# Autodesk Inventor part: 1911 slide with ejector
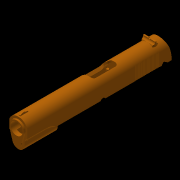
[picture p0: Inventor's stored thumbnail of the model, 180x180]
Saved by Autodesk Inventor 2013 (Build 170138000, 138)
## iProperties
Created: 2012-12
Part Number: 1911 slide with ejector
Material: Generic
Document SubType Name: Modeling
Designer: John
Density: 1 g/cm^3
Author: John
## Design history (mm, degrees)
sketch "Sketch1"
  geometry: L1 (-11.633, -12.598)-(-11.633, 4.424); L2 (11.633, -12.598)-(11.633, 4.424); L3 (-8.128, -16.129)-(-8.128, -12.598); L4 (8.128, -16.129)-(8.128, -12.598); L5 (-11.633, -12.598)-(-8.128, -12.598); L6 (8.128, -12.598)-(11.633, -12.598); C1 r 8.877 at (0, 0); C2 r 6.35 at (0, -16.129); A1 r 12.446 centre (0, 0) between (11.633, 4.424) and (-11.633, 4.424); A2 r 8.128 centre (0, -16.129) between (-8.128, -16.129) and (8.128, -16.129); 1 further point
  constraints: 12 end point, 4 centre point, 4 perpendicular, 4 point on circle, 3 coincident, 2 tangent
  dimensions: "d9" = 12.7 diameter of C2
extrude "Extrusion1" new body sketch "Sketch1" distance "d10" = 43.1292; taper "d11" = 0 deg
sketch "Sketch2"
  geometry: L1 (11.633, -12.598)-(11.633, 4.424) reference; L2 (-11.633, 4.424)-(-11.633, -12.598) reference; L3 (-8.877, 0)-(-8.877, -12.598); L4 (8.877, 0)-(8.877, -12.598); L5 (-11.633, -12.598)-(-8.877, -12.598); L6 (8.877, -12.598)-(11.633, -12.598); A1 r 8.877 centre (0, 0) between (-8.877, 0) and (8.877, 0) reference; A2 r 12.446 centre (0, 0) between (11.633, 4.424) and (-11.633, 4.424) reference
  constraints: 8 end point, 6 perpendicular, 2 point on circle, 2 tangent
extrude "Extrusion2" join sketch "Sketch2" distance "d12" = 138.6332; taper "d13" = 0 deg
sketch "Sketch3"
  geometry: L1 (181.762, 17.022)-(181.762, 0) reference; L2 (181.762, 17.022)-(181.762, 25.044) reference; L3 (181.762, 0)-(189.144, 0); A1 r 46.177 centre (142.967, 0) between (189.144, 0) and (181.762, 25.044); 1 further point
  constraints: 2 end point, 2 point on circle, 1 centre point, 1 perpendicular
extrude "Extrusion3" join sketch "Sketch3" stored distance "d15" = 24.892; taper "d16" = 0 deg
sketch "Sketch4"
  geometry: L1 (-11.633, -12.598)-(-11.633, 4.424) reference; L2 (11.633, 4.424)-(11.633, -12.598) reference; L3 (-11.633, 1.975)-(-14.32, 1.975); L4 (-14.32, 1.975)-(-14.32, 15.401); L5 (-14.32, 15.401)-(14.052, 15.401); L6 (14.052, 15.401)-(14.052, 2.651); L7 (14.052, 2.651)-(11.633, 2.651); A1 r 12.446 centre (0, 0) between (11.633, 4.424) and (-11.633, 4.424) reference
  constraints: 10 end point, 3 perpendicular, 2 parallel, 2 point on line
extrude "Extrusion4" cut sketch "Sketch4" stored distance "d17" = 24.892; taper "d18" = 0 deg
sketch "Sketch5"
  geometry: L1 (-19.761, 43.129)-(-19.761, -146.015) reference; L2 (3.505, -146.015)-(-19.761, -146.015) reference; L3 (3.505, 43.129)-(3.505, -146.015) reference; L4 (-16.256, 43.129)-(-16.256, 0) reference; L5 (3.505, -144.665)-(3.505, -148.55); L6 (3.505, -148.55)-(-19.761, -148.55); L7 (-19.761, -148.55)-(-19.761, -144.665); A1 r 50.8 centre (-8.128, -95.215) between (-19.761, -144.665) and (3.505, -144.665); A2 r 50.8 centre (-8.128, -95.215) between (3.505, -45.765) and (-19.761, -45.765); 1 further point
  constraints: 6 end point, 4 point on circle, 4 point on line, 2 centre point, 2 parallel, 1 perpendicular
sketch "Sketch6"
  geometry: A1 r 46.177 centre (-12.598, -142.967) between (-12.598, -189.144) and (12.446, -181.762); 1 further point
  constraints: 2 point on circle, 1 centre point
sketch "Sketch8"
  geometry: L1 (3.505, 43.129)-(0, 43.129) reference; L2 (5.944, 43.129)-(0, 43.129); L3 (5.944, 43.129)-(5.944, 1.079); L4 (5.944, 1.079)-(0, 1.079); L5 (0, 20.366)-(0, 43.129); A1 r 34.267 centre (34.267, 20.366) between (0, 20.366) and (5.944, 1.079); 1 further point
  constraints: 8 end point, 2 perpendicular, 2 point on circle, 1 centre point, 1 collinear, 1 tangent
revolve "Revolution1" sketch "Sketch8" stored, may be unused: angle "d23" = 90 deg
mirror "Mirror1"
sketch "Sketch9"
  geometry: L1 (-9.576, -9.601)-(9.576, -9.601); L2 (-11.633, 4.424)-(-11.633, -7.178) reference; L3 (-8.128, -12.598)-(-11.633, -12.598) reference; L4 (11.633, -7.178)-(11.633, 4.424) reference; L5 (11.633, -12.598)-(8.128, -12.598) reference; L6 (-11.633, -7.178)-(-11.633, -12.598); L7 (11.633, -12.598)-(11.633, -7.178); L8 (-9.576, -7.036)-(9.576, -7.036); L9 (-9.576, -9.601)-(-9.576, -7.036); L10 (9.576, -9.601)-(9.576, -7.036); A1 r 12.446 centre (0, 0) between (11.633, 4.424) and (-11.633, 4.424) reference; 1 further point
  constraints: 12 end point, 3 perpendicular, 1 parallel
extrude "Extrusion5" cut sketch "Sketch9" stored distance "d31" = 25.4; taper "d32" = 0 deg
sketch "Sketch10"
  geometry: L1 (12.446, 0)-(12.446, -181.762) reference; L2 (-12.598, -37.861)-(-12.598, -189.144) reference; L3 (12.446, -181.762)-(-12.598, -181.762); L4 (-12.598, -181.762)-(13.56, -181.762); L5 (13.56, -181.762)-(13.56, -201.516); L6 (13.56, -201.516)-(-12.598, -201.516); L7 (-12.598, -201.516)-(-12.598, -181.762); 2 further points
  constraints: 10 end point, 2 parallel, 2 perpendicular, 1 horizontal, 1 point on line
extrude "Extrusion6" cut sketch "Sketch10" stored distance "d33" = 8.001; taper "d34" = 0 deg
sketch "Sketch11"
  geometry: L1 (4.877, -2.565)-(4.877, -5.563) reference; L2 (-2.756, -5.563)-(4.877, -5.563) reference; L3 (-2.756, 11.46)-(-2.756, -5.563) reference; L4 (4.877, 18.821)-(4.877, 0) reference; L5 (4.877, 0)-(-0.698, 0) reference; L6 (-0.698, 0)-(-0.698, -2.565) reference; L7 (-0.698, -2.565)-(4.877, -2.565) reference; L8 (12.878, -5.563)-(12.878, -2.565) reference; L9 (12.878, -2.565)-(18.453, -2.565) reference; L10 (18.453, -2.565)-(18.453, 0) reference; L11 (18.453, 0)-(12.878, 0) reference; L12 (12.878, 0)-(12.878, 18.821) reference; L13 (20.511, -5.563)-(20.511, 11.46) reference; L14 (12.878, -5.563)-(20.511, -5.563) reference; L15 (17.755, 0)-(17.755, 7.036) reference; L16 (17.755, -5.563)-(17.755, -2.565) reference; L17 (0, -2.565)-(0, -5.563) reference; A1 r 8.877 centre (8.877, 7.036) between (17.755, 7.036) and (12.878, 14.961) reference
  constraints: 2 other
extrude "Extrusion7" cut sketch "Sketch11" stored distance "d35" = 8.001; taper "d36" = 0 deg
sketch "Sketch12"
  geometry: L1 (8.877, -12.598)-(8.877, -9.601) reference; L2 (7.988, -12.598)-(7.988, -9.601); L3 (7.988, -9.601)-(8.877, -9.601); L4 (7.988, -12.598)-(8.877, -12.598); L5 (0, -12.394)-(0, -11.1); L6 (-7.988, -12.598)-(-8.877, -12.598); L7 (-8.128, -12.598)-(-8.877, -12.598); L8 (-8.877, -12.598)-(-8.877, -9.601); L9 (-7.988, -12.598)-(-7.988, -9.601); L10 (-7.988, -9.601)-(-8.877, -9.601); L11 (-8.877, -9.601)-(-9.576, -9.601)
  constraints: 20 end point, 2 perpendicular, 2 symmetric about line
extrude "Extrusion8" join sketch "Sketch12" distance "d38" = 146.812; taper "d39" = 0 deg
sweep "Sweep2" dims "d40" = 0
workplane "Work Plane1"
sketch "Sketch13"
  geometry: L1 (5.537, -124.206)-(-5.537, -124.206); L2 (-5.537, -124.206)-(-5.537, -95.148); L3 (-1.575, -91.186)-(5.537, -91.186); L4 (5.537, -91.186)-(5.537, -124.206); A1 r 3.962 centre (-1.575, -95.148) between (-1.575, -91.186) and (-5.537, -95.148); 1 further point
  constraints: 8 end point, 2 point on circle, 2 tangent, 1 centre point, 1 parallel, 1 perpendicular
  dimensions: "d45" = 3.9624 radius of A1
sketch "Sketch14"
  geometry: L1 (4.648, -16.129)-(4.648, -7.563); L2 (4.648, -16.129)-(-4.648, -16.129); L3 (-4.648, -16.129)-(-4.648, -7.563); C1 r 6.35 at (0, -16.129) reference; A1 r 8.877 centre (0, 0) between (4.648, -7.563) and (-4.648, -7.563) reference
  constraints: 6 end point, 2 perpendicular, 2 point on circle
  dimensions: "d46" = 4.6482 distance of C1.centre L1.start; "d47" = 9.2964 distance of L1.start L2.end
extrude "Extrusion9" cut sketch "Sketch14" distance "d48" = 146.812; taper "d49" = 0 deg
extrude "Extrusion10" cut sketch "Sketch13" distance "d50" = 9.525; taper "d51" = 0 deg
workplane "Work Plane3"
sketch "Sketch15"
  geometry: L1 (91.186, -9.064)-(124.206, -9.064) reference; L2 (91.186, -9.064)-(120.142, -9.064); L3 (0, 0)-(184.436, 0) reference; L4 (120.142, -9.064)-(120.142, -3.962); L5 (91.186, -9.064)-(91.186, -3.962); L6 (95.148, 0)-(116.18, 0); L7 (124.206, -9.064)-(120.142, -9.064); A1 r 3.962 centre (116.18, -3.962) between (120.142, -3.962) and (116.18, 0); A2 r 3.962 centre (95.148, -3.962) between (95.148, 0) and (91.186, -3.962); 3 further points
  constraints: 10 end point, 7 point on line, 4 point on circle, 4 tangent, 2 centre point, 2 collinear, 1 equal radius, 1 parallel, 1 perpendicular
  dimensions: "d55" = 3.9624 radius of A1
extrude "Extrusion11" cut sketch "Sketch15" distance "d56" = 9.525; taper "d57" = 0 deg
fillet "Fillet1" dims "d58" = 3.175
sketch "Sketch16"
  geometry: L1 (-16.256, 0)-(0, 0) reference; L2 (3.505, -97.384)-(2.921, -98.83); L3 (2.921, -98.83)-(3.505, -99.048); L4 (3.505, -97.384)-(3.505, -99.048); 1 further point
  constraints: 6 end point
extrude "Extrusion12" cut sketch "Sketch16" stored distance "d65" = 25.4; taper "d66" = 0 deg
mirror "Mirror2"
sketch "Sketch17"
  geometry: L1 (4.424, 0)-(12.446, 0) reference; L2 (10.906, -1.575)-(13.297, -1.575); L3 (10.906, -6.858)-(10.906, -1.575); L4 (10.906, -6.858)-(10.906, -12.141); L5 (10.906, -12.141)-(13.32, -12.141); L6 (13.454, -11.731)-(13.323, -11.474); L7 (13.579, -11.344)-(13.323, -11.474); L8 (13.454, -11.731)-(13.32, -12.141); L9 (13.705, -10.958)-(13.449, -11.088); L10 (13.579, -11.344)-(13.449, -11.088); L11 (13.83, -10.571)-(13.574, -10.701); L12 (13.705, -10.958)-(13.574, -10.701); L13 (13.956, -10.184)-(13.7, -10.315); L14 (13.83, -10.571)-(13.7, -10.315); L15 (14.082, -9.798)-(13.825, -9.928); L16 (13.956, -10.184)-(13.825, -9.928); L17 (14.207, -9.411)-(13.951, -9.542); L18 (14.082, -9.798)-(13.951, -9.542); L19 (14.333, -9.025)-(14.077, -9.155); L20 (14.207, -9.411)-(14.077, -9.155); L21 (14.458, -8.638)-(14.202, -8.769); L22 (14.333, -9.025)-(14.202, -8.769); L23 (14.584, -8.252)-(14.328, -8.382); L24 (14.458, -8.638)-(14.328, -8.382); L25 (14.709, -7.865)-(14.453, -7.996); L26 (14.584, -8.252)-(14.453, -7.996); L27 (14.835, -7.479)-(14.579, -7.609); L28 (14.709, -7.865)-(14.579, -7.609); L29 (14.961, -7.092)-(14.705, -7.223); L30 (14.835, -7.479)-(14.705, -7.223); L31 (15.037, -6.858)-(14.961, -7.092); A1 r 8.89 centre (6.147, -6.858) between (15.037, -6.858) and (13.297, -1.575); 1 further point
  constraints: 60 end point, 14 perpendicular, 2 point on circle, 1 centre point, 1 collinear, 1 point on line
extrude "Extrusion13" join sketch "Sketch17" stored distance "d79" = 2.032; taper "d80" = 0 deg
sketch "Sketch18"
  geometry: L1 (124.206, 19.398)-(124.206, 19.624) reference; L2 (101.313, -3.507)-(101.487, -4.743); L3 (97.601, -3.033)-(100.478, -2.832); L4 (93.843, -5.42)-(102.266, -5.42); A1 r 0.787 centre (100.533, -3.617) between (101.313, -3.507) and (100.478, -2.832); A2 r 1.981 centre (97.739, -5.009) between (97.601, -3.033) and (95.972, -4.113); A3 r 2.388 centre (93.843, -3.033) between (93.843, -5.42) and (95.972, -4.113); A4 r 0.787 centre (102.266, -4.633) between (101.487, -4.743) and (102.266, -5.42); 2 further points
  constraints: 8 point on circle, 6 end point, 6 tangent, 4 centre point, 1 point on line
extrude "Extrusion14" cut sketch "Sketch18" distance "d90" = 2.413; taper "d91" = 0 deg
sketch "Sketch19"
  geometry: L1 (12.22, -124.206)-(12.446, -124.206) reference; L2 (-12.598, -43.129)-(-12.598, -188.512) reference; L3 (8.433, -175.773)-(8.433, -165.781); L4 (8.433, -173.276)-(8.433, -175.773); L5 (12.446, 0)-(12.446, -181.762) reference; L6 (9.525, -166.376)-(12.449, -167.74) reference; L7 (9.525, -175.177)-(12.449, -173.814) reference; L8 (9.525, -166.376)-(9.525, -175.177) reference; L9 (9.525, -171.539)-(9.525, -170.015); L10 (15.748, -171.539)-(15.479, -170.015) reference; L11 (14.834, -170.015)-(15.479, -170.015); L12 (15.748, -171.539)-(14.834, -171.539); A1 r 2.388 centre (14.834, -167.627) between (12.449, -167.74) and (14.834, -170.015); A2 r 2.388 centre (14.834, -173.927) between (14.834, -171.539) and (12.449, -173.814); 2 further points
  constraints: 18 end point, 4 point on circle, 2 centre point, 2 perpendicular, 2 point on line, 2 tangent, 1 horizontal, 1 midpoint, 1 vertical, 4 other
extrude "Extrusion15" join sketch "Sketch19" stored distance "d111" = 15.9004; taper "d112" = 0 deg
workplane "Work Plane4"
sketch "Sketch20"
  geometry: L1 (7.95, -166.4)-(7.95, -175.154) reference; L2 (-7.95, -175.154)-(-7.95, -166.4) reference; L3 (1.016, -1.575)-(1.016, -12.141) reference; L4 (1.016, -12.141)-(-1.016, -12.141) reference; L5 (-1.016, -12.141)-(-1.016, -1.575) reference; L6 (-1.016, -1.575)-(1.016, -1.575) reference; L7 (11.633, -172.136)-(11.049, -171.917) reference; L8 (11.049, -171.917)-(11.633, -170.471) reference; L9 (11.633, -170.471)-(11.049, -170.253) reference; L10 (11.049, -170.253)-(11.633, -168.807) reference; L11 (11.633, -168.807)-(11.049, -168.589) reference; L12 (11.049, -168.589)-(11.633, -167.143) reference; L13 (11.633, -167.143)-(11.049, -166.924) reference; L14 (11.049, -166.924)-(11.633, -165.478) reference; L15 (11.633, -165.478)-(11.049, -165.26) reference; L16 (11.049, -165.26)-(11.633, -163.814) reference; L17 (11.633, -163.814)-(11.049, -163.596) reference; L18 (11.049, -163.596)-(11.633, -162.15) reference; L19 (11.633, -162.15)-(11.049, -161.931) reference; L20 (11.049, -161.931)-(11.633, -160.485) reference; L21 (11.633, -160.485)-(11.049, -160.267) reference; L22 (11.049, -160.267)-(11.633, -158.821) reference; L23 (11.633, -158.821)-(11.049, -158.602) reference; L24 (11.049, -158.602)-(11.633, -157.156) reference; L25 (11.633, -157.156)-(11.049, -156.938) reference; L26 (11.049, -156.938)-(11.633, -155.492) reference; L27 (11.633, -155.492)-(11.049, -155.274) reference; L28 (11.049, -155.274)-(11.633, -153.828) reference; L29 (11.633, -153.828)-(11.049, -153.609) reference; L30 (11.049, -153.609)-(11.633, -152.163) reference; L31 (11.633, -152.163)-(11.049, -151.945) reference; L32 (11.049, -151.945)-(11.633, -150.499) reference; L33 (11.633, -150.499)-(11.049, -150.281) reference; L34 (11.049, -150.281)-(11.633, -148.835) reference; L35 (11.633, -148.835)-(11.049, -148.616) reference; L36 (11.049, -148.616)-(11.633, -147.17) reference; L37 (11.633, -147.17)-(11.049, -146.952) reference; L38 (11.049, -146.952)-(11.633, -145.506) reference; L39 (11.633, -145.506)-(11.049, -145.287) reference; L40 (11.049, -145.287)-(11.633, -143.842) reference; L41 (11.633, -143.842)-(11.049, -143.623) reference; L42 (11.049, -143.623)-(11.633, -142.177) reference; L43 (11.633, -142.177)-(11.049, -141.959) reference; L44 (11.049, -141.959)-(11.633, -140.513) reference; L45 (11.633, -116.18)-(11.633, -140.513) reference; L46 (9.567, -120.142)-(5.537, -120.142) reference; L47 (5.537, -120.142)-(5.537, -121.031) reference; L48 (2.362, -124.206)-(-2.362, -124.206) reference; L49 (-5.537, -121.031)-(-5.537, -95.148) reference; L50 (-1.575, -91.186)-(9.567, -91.186) reference; L51 (11.633, 0)-(11.633, -95.148) reference; L52 (11.633, 0)-(-11.633, 0) reference; L53 (-11.633, 0)-(-11.633, -140.513) reference; L54 (-11.633, -140.513)-(-11.049, -141.959) reference; L55 (-11.049, -141.959)-(-11.633, -142.177) reference; L56 (-11.633, -142.177)-(-11.049, -143.623) reference; L57 (-11.049, -143.623)-(-11.633, -143.842) reference; L58 (-11.633, -143.842)-(-11.049, -145.287) reference; L59 (-11.049, -145.287)-(-11.633, -145.506) reference; L60 (-11.633, -145.506)-(-11.049, -146.952) reference; L61 (-11.049, -146.952)-(-11.633, -147.17) reference; L62 (-11.633, -147.17)-(-11.049, -148.616) reference; L63 (-11.049, -148.616)-(-11.633, -148.835) reference; L64 (-11.633, -148.835)-(-11.049, -150.281) reference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; A1 r 7.874 centre (0, -170.777) between (6.794, -174.756) and (6.794, -166.797); A2 r 7.874 centre (0, -170.777) between (-6.794, -166.797) and (-6.794, -174.756); 3 further points; 2 other entities
  constraints: 4 point on circle, 2 centre point, 13 other
extrude "Extrusion16" cut sketch "Sketch20" stored distance "d115" = 15.9004; taper "d116" = 0 deg
sketch "Sketch21"
  geometry: L1 (15.674, 0)-(0, 0) reference; L2 (15.674, -0.914)-(0, -0.914) reference; L3 (7.837, 0)-(8.853, 0); L4 (8.853, 0)-(8.853, -1.016); L5 (8.853, -1.016)-(6.821, -1.016); L6 (6.821, -1.016)-(6.821, 0); 1 further point
  constraints: 8 end point, 2 perpendicular, 2 point on line, 1 midpoint, 1 parallel
  dimensions: "d117" = 1.016 distance of L3.start L3.end; "d118" = 1.016 distance of L3.end L4.end; "d119" = 2.032 distance of L4.end L5.end
extrude "Extrusion17" cut sketch "Sketch21" distance "d120" = 15.9004; taper "d121" = 0 deg
sketch "Sketch22"
  geometry: L1 (-37.861, -5.42)-(-140.513, -5.42) reference; L2 (-116.18, 11.602)-(-140.513, 11.602) reference; L3 (-47.574, -5.42)-(-47.574, -5.166); L4 (-47.574, -5.166)-(-11.382, -5.166); L5 (-11.382, -5.166)-(-11.382, -6.538); L6 (-11.382, -6.538)-(-47.574, -6.538); L7 (-47.574, -6.538)-(-47.574, -5.42); 1 further point
  constraints: 10 end point, 3 perpendicular, 2 parallel, 1 point on line
  dimensions: "d122" = 0.254 distance of L3.start L3.end
extrude "Extrusion18" cut sketch "Sketch22" stored distance "d124" = 25.4; taper "d125" = 0 deg
sketch "Sketch23"
  geometry: L1 (-47.574, -5.166)-(-37.834, -5.166) reference; L2 (-43.129, -8.951)-(-43.129, -5.42) reference; L3 (-43.129, -5.42)-(-43.129, -5.166); L4 (-43.129, -5.166)-(-189.167, -5.166); L5 (-189.167, -5.166)-(-189.167, -5.785); L6 (-189.167, -5.785)-(-43.129, -5.785); L7 (-43.129, -5.785)-(-43.129, -5.42); 1 further point
  constraints: 10 end point, 5 perpendicular, 2 point on line
mirror "Mirror3"
extrude "Extrusion19" cut sketch "Sketch23" distance "d126" = 25.4; taper "d127" = 0 deg
sketch "Sketch24"
  geometry: L1 (13.857, 14.915)-(67.695, 14.915); L2 (9.2, -2.465)-(6.411, -12.874); L3 (-9.2, -2.465)-(-6.411, -12.874); C1 r 7.379 at (0, 0); A1 r 9.525 centre (0, 0) between (9.2, -2.465) and (-9.2, -2.465) reference; A2 r 5.004 centre (0, -16.078) between (4.135, -13.261) and (-4.135, -13.261) reference; A3 r 1.27 centre (5.185, -12.545) between (4.135, -13.261) and (6.411, -12.874); A4 r 1.27 centre (-5.185, -12.545) between (-6.411, -12.874) and (-4.135, -13.261)
  constraints: 8 point on circle, 6 end point, 5 centre point, 3 tangent, 1 coincident, 1 horizontal, 2 other
  dimensions: "d140" = 14.7574 diameter of C1
extrude "Extrusion20" join sketch "Sketch24" distance "d141" = 2.3114; taper "d142" = 0 deg
sketch "Sketch25"
  geometry: L1 (-4.648, -7.563)-(-4.648, -11.803) reference; L2 (-4.648, -7.563)-(-4.648, -5.731); L3 (4.648, -7.563)-(4.648, -5.731); A1 r 8.877 centre (0, 0) between (4.648, -7.563) and (-4.648, -7.563) reference; A2 r 7.379 centre (0, 0) between (-4.648, -5.731) and (4.648, -5.731) reference
  constraints: 4 end point, 2 point on circle, 1 collinear, 1 parallel
extrude "Extrusion21" join sketch "Sketch25" stored distance "d143" = 2.3114; taper "d144" = 0 deg
sketch "Sketch27"
  geometry: C1 r 5.004 at (0, -16.078); A1 r 5.004 centre (0, -16.078) between (4.135, -13.261) and (-4.135, -13.261) reference
  constraints: 1 centre point, 1 coincident
extrude "Extrusion23" join sketch "Sketch27" distance "d147" = 1.524; taper "d148" = 0 deg
sketch "Sketch28"
  geometry: C1 r 6.35 at (0, -16.129); A1 r 6.35 centre (0, -16.129) between (-5.839, -13.634) and (5.839, -13.634) reference; A2 r 8.128 centre (0, -16.129) between (-8.128, -16.129) and (8.128, -16.129) reference; A3 r 5.004 centre (0, -16.078) between (-4.135, -13.261) and (4.135, -13.261) reference; A4 r 5.004 centre (0, -16.078) between (4.135, -13.261) and (-4.135, -13.261) reference
  constraints: 1 centre point, 1 coincident, 1 concentric
extrude "Extrusion24" join sketch "Sketch28" stored distance "d149" = 41.3385; taper "d150" = 0 deg
sketch "Sketch31"
  geometry: L1 (-4.877, 0)-(0, 0) reference; L2 (0, 0)-(0, 7.036) reference; L3 (-12.878, 0)-(-12.878, 14.961) reference; L4 (-17.755, 7.036)-(-17.755, 0) reference; L5 (-17.755, 0)-(-12.878, 0) reference; L6 (-12.878, 0)-(-4.877, 0); A1 r 8.877 centre (-8.877, 7.036) between (0, 7.036) and (-4.877, 14.961) reference; A2 r 8.877 centre (-8.877, 7.036) between (-12.878, 14.961) and (-17.755, 7.036) reference; A3 r 8.877 centre (-8.877, 7.036) between (0, 7.036) and (-17.755, 7.036)
  constraints: 2 end point, 2 point on circle, 2 point on line, 1 centre point, 1 coincident, 1 collinear, 1 concentric
extrude "Extrusion27" join sketch "Sketch31" stored distance "d158" = 55.5625; taper "d159" = 0 deg
workplane "Work Plane5"
sketch "Sketch32"
  geometry: L1 (18.453, -2.565)-(16.866, -2.565) reference; A1 r 8.877 centre (8.877, 7.036) between (17.755, 7.036) and (0, 7.036) reference; A2 r 8.877 centre (8.877, 8.369) between (17.73, 7.703) and (0.025, 7.703); 2 further points
  constraints: 4 point on circle, 1 centre point, 1 coincident
extrude "Extrusion28" cut sketch "Sketch32" distance "d163" = 4.5212; taper "d164" = 0 deg
workplane "Work Plane6"
sketch "Sketch33"
  geometry: L1 (-2.451, -16.54)-(-4.039, -16.54) reference; A1 r 8.877 centre (5.537, -5.605) between (14.389, -6.272) and (-3.315, -6.272); A2 r 8.877 centre (5.537, -6.939) between (14.389, -6.272) and (-3.315, -6.272) reference; 1 further point
  constraints: 4 point on circle, 1 centre point
extrude "Extrusion29" cut sketch "Sketch33" distance "d168" = 4.5212; taper "d169" = 0 deg
sketch "Sketch34"
  geometry: L1 (37.834, -5.166)-(47.574, -5.166) reference; L2 (47.574, -5.166)-(94.915, -5.166) reference; L3 (176.354, -2.313)-(174.501, -5.166); L4 (178.111, -1.94)-(183.079, -5.166) reference; L5 (174.501, -5.166)-(183.079, -5.166); A1 r 1.27 centre (177.419, -3.005) between (178.111, -1.94) and (176.354, -2.313) reference; 1 further point
  constraints: 6 end point, 2 point on circle, 2 point on line, 2 tangent, 1 centre point, 1 collinear, 1 perpendicular, 3 other
extrude "Extrusion30" cut sketch "Sketch34" distance "d183" = 7.6962; taper "d184" = 0 deg
sketch "Sketch35"
  geometry: A1 r 5.004 centre (0, -16.078) between (4.135, -13.261) and (-4.135, -13.261) reference; A2 r 5.004 centre (0, -16.078) between (-4.135, -13.261) and (4.135, -13.261) reference; 1 further point
extrude "Extrusion31" join sketch "Sketch35" distance "d185" = 3.175; taper "d186" = 0 deg
workplane "Work Plane7"
sketch "Sketch36"
  geometry: L1 (4.648, -11.803)-(4.648, -5.731) reference; L2 (-4.648, -5.731)-(-4.648, -11.803) reference; L3 (0, -16.078)-(5.004, -16.078); L4 (5.004, -16.078)-(5.004, -5.423); L5 (0, -16.078)-(-5.004, -16.078); L6 (-5.004, -16.078)-(-5.004, -5.423); A1 r 6.35 centre (0, -16.129) between (4.648, -11.803) and (-4.648, -11.803) reference; A2 r 7.379 centre (0, 0) between (4.648, -5.731) and (-4.648, -5.731) reference; A3 r 5.004 centre (0, -16.078) between (5.004, -16.078) and (-5.004, -16.078) reference; 1 further point
  constraints: 8 end point, 4 point on circle, 3 perpendicular, 2 tangent, 1 parallel
extrude "Extrusion32" cut sketch "Sketch36" stored distance "d188" = 12.7; taper "d189" = 0 deg
sketch "Sketch37"
  geometry: L1 (0, 0)-(6.35, 0); L2 (6.35, 0)-(6.35, -9.525); L3 (6.35, -9.525)-(-6.35, -9.525); L4 (-6.35, -9.525)-(-6.35, 0); L5 (-6.35, 0)-(0, 0); 1 further point
  constraints: 10 end point, 2 parallel, 2 perpendicular
  dimensions: "d190" = 6.35 distance of L1.start L1.end; "d192" = 12.7 distance of L2.end L3.end
extrude "Extrusion33" cut sketch "Sketch37" distance "d193" = 25.4; taper "d194" = 0 deg
sketch "Sketch38"
  geometry: C1 r 7.379 at (0, 0) reference; C2 r 7.874 at (0, 0); A1 r 9.525 centre (0, 0) between (9.2, -2.465) and (-9.2, -2.465) reference
  constraints: 1 centre point, 1 coincident
  dimensions: "d195" = 15.748 diameter of C2
extrude "Extrusion34" cut sketch "Sketch38" distance "d197" = 55.5625; taper "d198" = 0 deg
sketch "Sketch39"
  geometry: L1 (0, 0)-(17.755, 0) reference; L2 (11.239, 19.256)-(11.239, 15.593) reference; L3 (0, 0)-(0, -7.053); L4 (0, -7.053)-(17.755, -7.053); L5 (17.755, -7.053)-(17.755, 0)
  constraints: 6 end point, 2 parallel, 1 perpendicular
extrude "Extrusion35" cut sketch "Sketch39" distance "d199" = 76.2; taper "d200" = 0 deg
sketch "Sketch40"
  geometry: L1 (-11.633, -12.344)-(-11.633, -12.09); L2 (-11.633, -12.09)-(11.633, -12.09); L3 (11.633, -12.09)-(11.633, -12.344); L4 (11.633, -12.344)-(-11.633, -12.344); 3 further points
  constraints: 8 end point, 2 horizontal alignment, 2 perpendicular, 1 parallel, 1 vertical
  dimensions: "d201" = 0.254 distance of L1.start L1.end
extrude "Extrusion36" cut sketch "Sketch40" stored distance "d202" = 25.4; taper "d203" = 0 deg
sketch "Sketch41"
  geometry: L1 (11.633, -12.09)-(7.988, -12.09) reference; L2 (8.128, -12.344)-(11.633, -12.344) reference; L3 (8.128, -12.344)-(8.128, -12.09); L4 (11.633, -12.09)-(11.633, -12.344); L5 (0, -9.357)-(0, -11.651); L6 (-11.633, -12.09)-(-11.633, -12.344); L7 (-8.128, -12.344)-(-8.128, -12.09); L8 (-11.633, -12.09)-(-8.128, -12.09); L9 (-8.128, -12.344)-(-11.633, -12.344); 2 further points
  constraints: 14 end point, 5 symmetric about line, 2 parallel, 1 perpendicular, 1 point on line
extrude "Extrusion37" cut sketch "Sketch41" distance "d204" = 85.725; taper "d205" = 0 deg
sketch "Sketch43"
  geometry: L1 (17.755, 7.036)-(17.755, 0) reference; L2 (12.484, 0)-(12.484, 6.096); L3 (12.484, 6.096)-(14.795, 6.096); L4 (14.795, 3.632)-(14.795, 6.096); L5 (16.726, 0)-(16.726, 3.632); L6 (16.726, 3.632)-(14.795, 3.632); L7 (12.484, 0)-(16.726, 0)
  constraints: 12 end point, 2 parallel, 1 perpendicular
extrude "Extrusion39" cut sketch "Sketch43" stored distance "d214" = 25.4; taper "d215" = 0 deg
sketch "Sketch44"
  geometry: L1 (-17.755, 0)-(-5.271, 0) reference; L2 (-16.726, 0)-(-16.726, 3.429); L3 (-16.726, 3.429)-(-12.154, 3.429); L4 (-12.154, 3.429)-(-12.154, 0); L5 (-16.726, 0)-(-12.154, 0)
  constraints: 8 end point, 1 collinear, 1 perpendicular, 1 point on line
  dimensions: "d218" = 3.429 distance of L2.start L2.end; "d219" = 4.572 distance of L2.end L3.end
extrude "Extrusion40" cut sketch "Sketch44" distance "d220" = 50.8; taper "d221" = 0 deg
sketch "Sketch45"
  geometry: L1 (8.877, 0)-(8.877, -7.036) reference; L2 (-8.877, -7.036)-(-8.877, 0) reference; L3 (5.004, -16.078)-(5.004, -9.525) reference; L4 (-5.004, -9.525)-(-5.004, -16.078) reference; L5 (6.35, -9.525)-(6.35, -4.656) reference; L6 (5.004, -9.525)-(6.35, -9.525) reference; L7 (-6.35, -4.656)-(-6.35, -9.525) reference; L8 (9.576, -9.601)-(7.988, -9.601) reference; L9 (8.877, -7.036)-(8.877, -9.601); L10 (-7.988, -9.601)-(-9.576, -9.601) reference; L11 (-8.877, -7.036)-(-8.877, -9.601); L12 (7.988, -9.601)-(5.004, -9.601); L13 (-7.988, -9.601)-(-5.004, -9.601); L14 (-5.004, -9.525)-(-6.35, -9.525); A1 r 7.874 centre (0, 0) between (6.35, -4.656) and (-6.35, -4.656) reference; A2 r 8.877 centre (0, 0) between (8.877, 0) and (-8.877, 0) reference; A3 r 5.004 centre (0, -16.078) between (-5.004, -16.078) and (5.004, -16.078) reference; 1 further point
  constraints: 10 end point, 4 perpendicular, 4 point on line, 1 parallel
extrude "Extrusion41" cut sketch "Sketch45" stored distance "d222" = 25.4; taper "d223" = 0 deg
sketch "Sketch46"
  geometry: L1 (-4.648, -6.356)-(-4.648, -11.803) reference; L2 (4.648, -11.803)-(4.648, -6.356) reference; A1 r 7.874 centre (0, 0) between (-4.648, -6.356) and (4.648, -6.356) reference; A2 r 6.35 centre (0, -16.129) between (4.648, -11.803) and (-4.648, -11.803) reference
extrude "Extrusion42" join sketch "Sketch46" stored distance "d224" = 25.4; taper "d225" = 0 deg
sketch "Sketch47"
  geometry: L1 (0, -24.257)-(0, -21.082); L2 (6.591, -16.078)-(6.591, -9.601); L3 (-6.591, -16.078)-(-6.591, -9.601); L4 (6.591, -9.601)-(5.004, -9.601); L5 (5.004, -9.601)-(5.004, -16.078); L6 (-5.004, -16.078)-(-5.004, -9.601); L7 (-5.004, -9.601)-(-6.591, -9.601); A1 r 6.591 centre (0, -16.078) between (-6.591, -16.078) and (6.591, -16.078); A2 r 5.004 centre (0, -16.078) between (-5.004, -16.078) and (5.004, -16.078); 1 further point
  constraints: 14 end point, 4 point on circle, 3 perpendicular, 3 tangent, 2 centre point, 1 coincident, 1 parallel
extrude "Extrusion43" cut sketch "Sketch47" stored distance "d226" = 25.4; taper "d227" = 0 deg
sketch "Sketch48"
  geometry: A1 r 8.877 centre (1.575, -7.403) between (10.427, -8.07) and (-7.277, -8.07) reference; A2 r 8.877 centre (1.575, -8.737) between (10.427, -8.07) and (-7.277, -8.07) reference; 2 further points
  constraints: 2 point on circle
extrude "Extrusion44" cut sketch "Sketch48" stored distance "d228" = 25.4; taper "d229" = 0 deg
workplane "Work Plane8"
workplane "Work Plane9"
workplane "Work Plane10"
sketch "Sketch51"
  geometry: L1 (-2.635, -50.952)-(2.635, -50.952) reference; L2 (0, -50.952)-(0, 3.912); 1 further point
  constraints: 2 end point, 1 midpoint, 1 perpendicular
  dimensions: "d240" = 54.864 distance of L2.start L2.end
workplane "Work Plane11"
sketch "Sketch52"
  geometry: L1 (50.945, -0.98)-(53.722, -0.98); L2 (52.395, 2.349)-(53.273, 2.349); L3 (52.395, 1.179)-(52.395, 2.349); L4 (52.395, 1.179)-(50.945, 1.179); L5 (50.945, 1.179)-(50.945, -0.98); A1 r 3.429 centre (50.535, 0.285) between (53.722, -0.98) and (53.273, 2.349); 3 further points
  constraints: 10 end point, 3 perpendicular, 2 point on circle, 1 centre point
  dimensions: "d254" = 1.45 distance of L3.start L4.end; "d256" = 0.87821 distance of L2.start L2.end
extrude "Extrusion47" join sketch "Sketch52" stored distance "d249" = 6.2738; taper "d250" = 0 deg
sketch "Sketch53"
  geometry: L1 (-12.154, 3.429)-(-12.154, 0) reference; L2 (-12.154, 0)-(-5.271, 0) reference; L3 (-5.271, 0)-(-5.271, 6.096) reference; L4 (-5.271, 6.096)-(-2.959, 6.096) reference; L5 (-2.959, 6.096)-(-2.959, 3.632) reference; L6 (-2.959, 3.632)-(-1.029, 3.632) reference; L7 (-1.029, 3.632)-(-1.029, 0) reference; L8 (-1.029, 0)-(0, 0) reference; L9 (0, 7.036)-(0, 0) reference; L10 (-6.515, 19.256)-(-6.515, 16.927) reference; L11 (-11.24, 16.927)-(-11.24, 19.256) reference; L12 (-17.755, 0)-(-17.755, 7.036) reference; L13 (-17.755, 0)-(-16.726, 0) reference; L14 (-16.726, 0)-(-16.726, 3.429) reference; L15 (-16.726, 3.429)-(-12.154, 3.429) reference; L16 (-16.703, 4.686)-(-16.703, 10.96) reference; L17 (-14.544, 10.96)-(-14.544, 4.686) reference; L18 (-15.241, 8.646)-(-13.438, 8.646); L19 (-13.438, 8.646)-(-13.438, 6.842); L20 (-15.241, 8.646)-(-16.703, 8.646); A1 r 8.877 centre (-8.877, 7.036) between (0, 7.036) and (-0.025, 7.703) reference; A2 r 8.877 centre (-8.877, 8.369) between (-0.025, 7.703) and (-6.515, 16.927) reference; A3 r 12.446 centre (-8.877, 7.036) between (-6.515, 19.256) and (-11.24, 19.256) reference; A4 r 8.877 centre (-8.877, 8.369) between (-11.24, 16.927) and (-17.73, 7.703) reference; A5 r 1.803 centre (-15.241, 6.842) between (-16.703, 7.899) and (-13.438, 6.842); A6 r 8.877 centre (-8.877, 7.036) between (-17.73, 7.703) and (-17.755, 7.036) reference
  constraints: 6 end point, 3 tangent, 2 perpendicular, 2 point on circle, 2 point on line, 1 centre point
  dimensions: "d251" = 3.6068 diameter of A5
extrude "Extrusion48" cut sketch "Sketch53" distance "d252" = 7.5057; taper "d253" = 0 deg
body "Solid1"
pattern_linear "Rectangular Pattern1" dims "d69" = 1.66437
node "Projected Loop3"
node "Projected Loop4"
node "Projected Loop6"
node "Projected Loop7"
other parameters: "d113" = 4.7625, "d133" = 105 deg, "d138" = 105 deg, "d160" = 37.1348, "d165" = 41.4274, "d187" = -43.1292, "d241" = 90 deg
